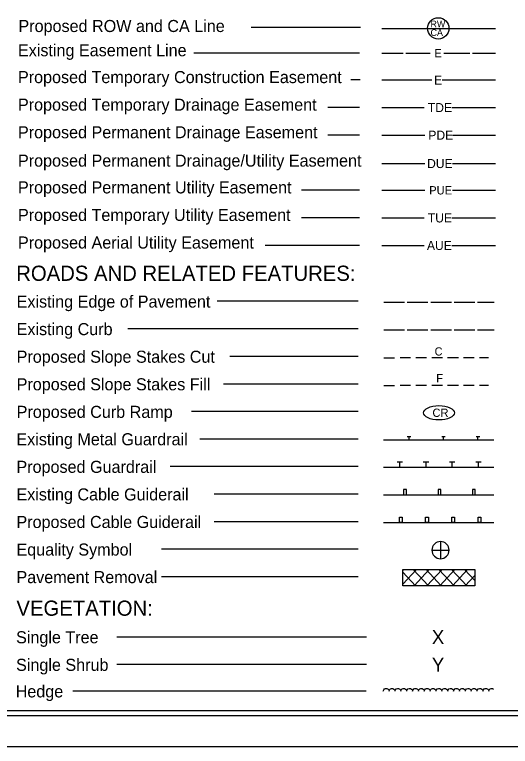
# Model space of a CAD drawing. Extents: x 2041685 to 2043369, y 619046 to 620146.
# Drawn here: x 2042248 to 2042607, y 619046 to 619576 of the extents above; entities that cross this region are included whole.
import ezdxf

# ---------------------------------------------------------------- set-up
doc = ezdxf.new("R2010")
doc.units = 0
for name, color, linetype in [('Prop Easement Permanent Drainage Utility', 7, 'Continuous'), ('Prop WCC CELL', 7, 'Continuous'), ('Sheet Cutting Line CELL', 7, 'Continuous'), ('Sheet Plot Border Inside CELL', 7, 'Continuous'), ('Sheet Plot Border Outside CELL', 7, 'Continuous'), ('Sheet Symbology CELL', 7, 'Continuous')]:
    doc.layers.add(name, color=color, linetype=linetype)

msp = doc.modelspace()

# ---------------------------------------------------------------- linework, layer by layer
at = {"layer": 'Prop Easement Permanent Drainage Utility'}
for p, q in [((2042513.91, 619468.39), (2042545.21, 619468.39)), ((2042565.21, 619468.39), (2042596.41, 619468.39))]:
    msp.add_line(p, q, dxfattribs=at)
at = {"layer": 'Prop WCC CELL'}
msp.add_ellipse((2042555.41, 619287.57), major_axis=(11.21, 0), ratio=0.462467, dxfattribs=at)
at = {"layer": 'Sheet Cutting Line CELL'}
msp.add_line((2041685.03, 619045.62), (2043369.03, 619045.62), dxfattribs=at)
at = {"layer": 'Sheet Plot Border Inside CELL'}
msp.add_lwpolyline([(2041698.03, 619068.07), (2043364.53, 619068.07), (2043364.53, 620123.17), (2041698.03, 620123.17)], close=True, dxfattribs=at)
at = {"layer": 'Sheet Plot Border Outside CELL'}
msp.add_lwpolyline([(2041685.03, 619045.62), (2043369.03, 619045.62), (2043369.03, 620145.62), (2041685.03, 620145.62)], close=True, dxfattribs=at)
at = {"layer": 'Sheet Symbology CELL'}
for p, q in [((2042498.51, 619567.04), (2042419.15, 619567.04)), ((2042513.92, 619566.27), (2042596.42, 619566.27)), ((2042497.88, 619548.42), (2042377.6, 619548.42)), ((2042513.91, 619548.42), (2042529.42, 619548.42)), ((2042531.42, 619548.42), (2042548.92, 619548.42)), ((2042558.92, 619548.42), (2042577.67, 619548.42)), ((2042579.67, 619548.42), (2042596.41, 619548.42)), ((2042498.27, 619528.97), (2042491.59, 619528.97)), ((2042513.91, 619528.97), (2042516.52, 619528.97)), ((2042516.52, 619528.97), (2042550.27, 619528.97)), ((2042557.77, 619528.97), (2042591.52, 619528.97)), ((2042591.52, 619528.97), (2042596.41, 619528.97)), ((2042497.88, 619508.97), (2042474.73, 619508.97)), ((2042513.91, 619508.97), (2042517.26, 619508.97)), ((2042517.26, 619508.97), (2042544.76, 619508.97)), ((2042564.76, 619508.97), (2042592.26, 619508.97)), ((2042592.26, 619508.97), (2042596.41, 619508.97)), ((2042497.88, 619488.97), (2042474.73, 619488.97)), ((2042513.91, 619488.97), (2042517.71, 619488.97)), ((2042517.71, 619488.97), (2042545.21, 619488.97)), ((2042565.21, 619488.97), (2042592.71, 619488.97)), ((2042592.71, 619488.97), (2042596.41, 619488.97)), ((2042497.88, 619448.96), (2042455.74, 619448.96)), ((2042513.91, 619448.96), (2042517.75, 619448.96)), ((2042517.75, 619448.96), (2042545.25, 619448.96)), ((2042565.25, 619448.96), (2042592.75, 619448.96)), ((2042592.75, 619448.96), (2042596.41, 619448.96)), ((2042497.88, 619428.96), (2042455.74, 619428.96)), ((2042513.91, 619428.96), (2042517.26, 619428.96)), ((2042517.26, 619428.96), (2042544.76, 619428.96)), ((2042564.76, 619428.96), (2042592.26, 619428.96)), ((2042592.26, 619428.96), (2042596.41, 619428.96)), ((2042497.88, 619408.96), (2042429.43, 619408.96)), ((2042513.91, 619408.96), (2042517.26, 619408.96)), ((2042517.26, 619408.96), (2042544.76, 619408.96)), ((2042564.76, 619408.96), (2042592.26, 619408.96)), ((2042592.26, 619408.96), (2042596.41, 619408.96)), ((2042496.92, 619368.43), (2042394.57, 619368.43)), ((2042515.45, 619367.86), (2042530.45, 619367.86)), ((2042532.45, 619367.86), (2042547.45, 619367.86)), ((2042549.45, 619367.86), (2042564.45, 619367.86)), ((2042566.45, 619367.86), (2042581.45, 619367.86)), ((2042583.45, 619367.86), (2042595.45, 619367.86)), ((2042496.92, 619348.43), (2042329.77, 619348.43)), ((2042515.45, 619347.86), (2042530.45, 619347.86)), ((2042532.45, 619347.86), (2042547.45, 619347.86)), ((2042549.45, 619347.86), (2042564.45, 619347.86)), ((2042566.45, 619347.86), (2042581.45, 619347.86)), ((2042583.45, 619347.86), (2042595.45, 619347.86)), ((2042496.92, 619328.43), (2042403.73, 619328.43)), ((2042515.45, 619327.38), (2042523.05, 619327.38)), ((2042534.75, 619327.38), (2042527.2, 619327.38)), ((2042546.25, 619327.38), (2042538.65, 619327.38)), ((2042558, 619327.38), (2042550.2, 619327.38)), ((2042569.45, 619327.38), (2042561.7, 619327.38)), ((2042581, 619327.38), (2042573.15, 619327.38)), ((2042591.3, 619327.38), (2042584.9, 619327.38)), ((2042496.92, 619308.43), (2042399.18, 619308.43)), ((2042515.45, 619307.38), (2042523.05, 619307.38)), ((2042534.75, 619307.38), (2042527.2, 619307.38)), ((2042546.25, 619307.38), (2042538.65, 619307.38)), ((2042558, 619307.38), (2042550.2, 619307.38)), ((2042569.45, 619307.38), (2042561.7, 619307.38)), ((2042581, 619307.38), (2042573.15, 619307.38)), ((2042591.3, 619307.38), (2042584.9, 619307.38)), ((2042496.92, 619288.43), (2042375.99, 619288.43)), ((2042496.76, 619268.55), (2042381.93, 619268.55)), ((2042515.29, 619267.98), (2042595.29, 619267.98)), ((2042532.43, 619270.48), (2042534.93, 619270.48)), ((2042533.68, 619267.98), (2042533.68, 619270.48)), ((2042557.43, 619270.48), (2042559.93, 619270.48)), ((2042558.68, 619267.98), (2042558.68, 619270.48)), ((2042582.43, 619270.48), (2042584.93, 619270.48)), ((2042583.68, 619267.98), (2042583.68, 619270.48)), ((2042525.02, 619251.93), (2042529.02, 619251.93)), ((2042527.02, 619247.98), (2042527.02, 619251.93)), ((2042544.02, 619251.93), (2042548.02, 619251.93)), ((2042546.02, 619247.98), (2042546.02, 619251.93)), ((2042563.02, 619251.93), (2042567.02, 619251.93)), ((2042565.02, 619247.98), (2042565.02, 619251.93)), ((2042582.02, 619251.93), (2042586.02, 619251.93)), ((2042584.02, 619247.98), (2042584.02, 619251.93)), ((2042496.76, 619248.55), (2042360.53, 619248.55)), ((2042595.29, 619247.98), (2042515.29, 619247.98)), ((2042496.76, 619228.55), (2042392.46, 619228.55)), ((2042515.29, 619227.98), (2042595.29, 619227.98)), ((2042496.76, 619208.55), (2042392.46, 619208.55)), ((2042515.29, 619207.98), (2042595.29, 619207.98)), ((2042556.52, 619194.21), (2042556.52, 619187.96)), ((2042496.76, 619188.55), (2042354.14, 619188.55)), ((2042550.27, 619187.96), (2042556.52, 619187.96)), ((2042556.52, 619187.96), (2042556.52, 619181.71)), ((2042556.52, 619187.96), (2042562.77, 619187.96)), ((2042529.24, 619173.84), (2042581.34, 619173.84)), ((2042529.24, 619162.14), (2042529.24, 619173.84)), ((2042529.24, 619173.24), (2042529.79, 619173.84)), ((2042529.24, 619163.29), (2042539.09, 619173.84)), ((2042538.49, 619162.14), (2042529.24, 619172.04)), ((2042547.79, 619162.14), (2042536.79, 619173.84)), ((2042537.39, 619162.14), (2042548.39, 619173.84)), ((2042557.04, 619162.14), (2042546.09, 619173.84)), ((2042546.64, 619162.14), (2042557.69, 619173.84)), ((2042566.34, 619162.14), (2042555.34, 619173.84)), ((2042555.94, 619162.14), (2042566.94, 619173.84)), ((2042575.64, 619162.14), (2042564.59, 619173.84)), ((2042565.24, 619162.14), (2042576.19, 619173.84)), ((2042581.34, 619165.89), (2042573.89, 619173.84)), ((2042581.34, 619173.84), (2042581.34, 619162.14)), ((2042496.76, 619168.55), (2042354.14, 619168.55)), ((2042574.49, 619162.14), (2042581.34, 619169.44)), ((2042581.34, 619162.14), (2042529.24, 619162.14)), ((2042502.9, 619124.91), (2042321.78, 619124.91)), ((2042502.9, 619104.91), (2042321.78, 619104.91)), ((2042502.63, 619085.65), (2042289.95, 619085.65)), ((2042515.03, 619085.65), (2042515.33, 619086.6)), ((2042515.33, 619086.6), (2042515.93, 619087.25)), ((2042515.93, 619087.25), (2042516.73, 619087.7)), ((2042516.73, 619087.7), (2042517.68, 619087.7)), ((2042517.68, 619087.7), (2042518.48, 619087.2)), ((2042518.48, 619087.2), (2042519.03, 619086.55)), ((2042519.03, 619086.55), (2042519.23, 619085.7)), ((2042519.28, 619085.65), (2042519.58, 619086.6)), ((2042519.58, 619086.6), (2042520.18, 619087.25)), ((2042520.18, 619087.25), (2042520.98, 619087.7)), ((2042520.98, 619087.7), (2042521.93, 619087.7)), ((2042521.93, 619087.7), (2042522.73, 619087.2)), ((2042522.73, 619087.2), (2042523.28, 619086.55)), ((2042523.28, 619086.55), (2042523.48, 619085.7)), ((2042523.53, 619085.65), (2042523.83, 619086.6)), ((2042523.83, 619086.6), (2042524.43, 619087.25)), ((2042524.43, 619087.25), (2042525.23, 619087.7)), ((2042525.23, 619087.7), (2042526.18, 619087.7)), ((2042526.18, 619087.7), (2042526.98, 619087.2)), ((2042526.98, 619087.2), (2042527.53, 619086.55)), ((2042527.53, 619086.55), (2042527.73, 619085.7)), ((2042527.78, 619085.65), (2042528.08, 619086.6)), ((2042528.08, 619086.6), (2042528.68, 619087.25)), ((2042528.68, 619087.25), (2042529.48, 619087.7)), ((2042529.48, 619087.7), (2042530.43, 619087.7)), ((2042530.43, 619087.7), (2042531.23, 619087.2)), ((2042531.23, 619087.2), (2042531.78, 619086.55)), ((2042531.78, 619086.55), (2042531.98, 619085.7)), ((2042532.03, 619085.65), (2042532.33, 619086.6)), ((2042532.33, 619086.6), (2042532.93, 619087.25)), ((2042532.93, 619087.25), (2042533.73, 619087.7)), ((2042533.73, 619087.7), (2042534.68, 619087.7)), ((2042534.68, 619087.7), (2042535.48, 619087.2)), ((2042535.48, 619087.2), (2042536.03, 619086.55)), ((2042536.03, 619086.55), (2042536.23, 619085.7)), ((2042536.28, 619085.65), (2042536.58, 619086.6)), ((2042536.58, 619086.6), (2042537.18, 619087.25)), ((2042537.18, 619087.25), (2042537.98, 619087.7)), ((2042537.98, 619087.7), (2042538.93, 619087.7)), ((2042538.93, 619087.7), (2042539.73, 619087.2)), ((2042539.73, 619087.2), (2042540.28, 619086.55)), ((2042540.28, 619086.55), (2042540.48, 619085.7)), ((2042540.53, 619085.65), (2042540.83, 619086.6)), ((2042540.83, 619086.6), (2042541.43, 619087.25)), ((2042541.43, 619087.25), (2042542.23, 619087.7)), ((2042542.23, 619087.7), (2042543.18, 619087.7)), ((2042543.18, 619087.7), (2042543.98, 619087.2)), ((2042543.98, 619087.2), (2042544.53, 619086.55)), ((2042544.53, 619086.55), (2042544.73, 619085.7)), ((2042544.78, 619085.65), (2042545.08, 619086.6)), ((2042545.08, 619086.6), (2042545.68, 619087.25)), ((2042545.68, 619087.25), (2042546.48, 619087.7)), ((2042546.48, 619087.7), (2042547.43, 619087.7)), ((2042547.43, 619087.7), (2042548.23, 619087.2)), ((2042548.23, 619087.2), (2042548.78, 619086.55)), ((2042548.78, 619086.55), (2042548.98, 619085.7)), ((2042549.03, 619085.65), (2042549.33, 619086.6)), ((2042549.33, 619086.6), (2042549.93, 619087.25)), ((2042549.93, 619087.25), (2042550.73, 619087.7)), ((2042550.73, 619087.7), (2042551.68, 619087.7)), ((2042551.68, 619087.7), (2042552.48, 619087.2)), ((2042552.48, 619087.2), (2042553.03, 619086.55)), ((2042553.03, 619086.55), (2042553.23, 619085.7)), ((2042553.28, 619085.65), (2042553.58, 619086.6)), ((2042553.58, 619086.6), (2042554.18, 619087.25)), ((2042554.18, 619087.25), (2042554.98, 619087.7)), ((2042554.98, 619087.7), (2042555.93, 619087.7)), ((2042555.93, 619087.7), (2042556.73, 619087.2)), ((2042556.73, 619087.2), (2042557.28, 619086.55)), ((2042557.28, 619086.55), (2042557.48, 619085.7)), ((2042557.53, 619085.65), (2042557.83, 619086.6)), ((2042557.83, 619086.6), (2042558.43, 619087.25)), ((2042558.43, 619087.25), (2042559.23, 619087.7)), ((2042559.23, 619087.7), (2042560.18, 619087.7)), ((2042560.18, 619087.7), (2042560.98, 619087.2)), ((2042560.98, 619087.2), (2042561.53, 619086.55)), ((2042561.53, 619086.55), (2042561.73, 619085.7)), ((2042561.78, 619085.65), (2042562.08, 619086.6)), ((2042562.08, 619086.6), (2042562.68, 619087.25)), ((2042562.68, 619087.25), (2042563.48, 619087.7)), ((2042563.48, 619087.7), (2042564.43, 619087.7)), ((2042564.43, 619087.7), (2042565.23, 619087.2)), ((2042565.23, 619087.2), (2042565.78, 619086.55)), ((2042565.78, 619086.55), (2042565.98, 619085.7)), ((2042566.03, 619085.65), (2042566.33, 619086.6)), ((2042566.33, 619086.6), (2042566.93, 619087.25)), ((2042566.93, 619087.25), (2042567.73, 619087.7)), ((2042567.73, 619087.7), (2042568.68, 619087.7)), ((2042568.68, 619087.7), (2042569.48, 619087.2)), ((2042569.48, 619087.2), (2042570.03, 619086.55)), ((2042570.03, 619086.55), (2042570.23, 619085.7)), ((2042570.28, 619085.65), (2042570.58, 619086.6)), ((2042570.58, 619086.6), (2042571.18, 619087.25)), ((2042571.18, 619087.25), (2042571.98, 619087.7)), ((2042571.98, 619087.7), (2042572.93, 619087.7)), ((2042572.93, 619087.7), (2042573.73, 619087.2)), ((2042573.73, 619087.2), (2042574.28, 619086.55)), ((2042574.28, 619086.55), (2042574.48, 619085.7)), ((2042574.53, 619085.65), (2042574.83, 619086.6)), ((2042574.83, 619086.6), (2042575.43, 619087.25)), ((2042575.43, 619087.25), (2042576.23, 619087.7)), ((2042576.23, 619087.7), (2042577.18, 619087.7)), ((2042577.18, 619087.7), (2042577.98, 619087.2)), ((2042577.98, 619087.2), (2042578.53, 619086.55)), ((2042578.53, 619086.55), (2042578.73, 619085.7)), ((2042578.78, 619085.65), (2042579.08, 619086.6)), ((2042579.08, 619086.6), (2042579.68, 619087.25)), ((2042579.68, 619087.25), (2042580.48, 619087.7)), ((2042580.48, 619087.7), (2042581.43, 619087.7)), ((2042581.43, 619087.7), (2042582.23, 619087.2)), ((2042582.23, 619087.2), (2042582.78, 619086.55)), ((2042582.78, 619086.55), (2042582.98, 619085.7)), ((2042583.03, 619085.65), (2042583.33, 619086.6)), ((2042583.33, 619086.6), (2042583.93, 619087.25)), ((2042583.93, 619087.25), (2042584.73, 619087.7)), ((2042584.73, 619087.7), (2042585.68, 619087.7)), ((2042585.68, 619087.7), (2042586.48, 619087.2)), ((2042586.48, 619087.2), (2042587.03, 619086.55)), ((2042587.03, 619086.55), (2042587.23, 619085.7)), ((2042587.28, 619085.65), (2042587.58, 619086.6)), ((2042587.58, 619086.6), (2042588.18, 619087.25)), ((2042588.18, 619087.25), (2042588.98, 619087.7)), ((2042588.98, 619087.7), (2042589.93, 619087.7)), ((2042589.93, 619087.7), (2042590.73, 619087.2)), ((2042590.73, 619087.2), (2042591.28, 619086.55)), ((2042591.28, 619086.55), (2042591.48, 619085.7)), ((2042591.53, 619085.65), (2042591.83, 619086.6)), ((2042591.83, 619086.6), (2042592.43, 619087.25)), ((2042592.43, 619087.25), (2042593.23, 619087.7)), ((2042593.23, 619087.7), (2042594.18, 619087.7)), ((2042594.18, 619087.7), (2042594.98, 619087.2)), ((2042594.98, 619087.2), (2042595.03, 619087.15))]:
    msp.add_line(p, q, dxfattribs=at)
for points in [[(2043352.03, 620120.62), (2041852.03, 620120.62), (2041852.03, 619071.63), (2043352.03, 619071.63)], [(2042529.77, 619227.98), (2042531.77, 619227.98), (2042531.77, 619231.98), (2042529.77, 619231.98)], [(2042554.77, 619227.98), (2042556.77, 619227.98), (2042556.77, 619231.98), (2042554.77, 619231.98)], [(2042579.77, 619227.98), (2042581.77, 619227.98), (2042581.77, 619231.98), (2042579.77, 619231.98)], [(2042526.76, 619211.98), (2042528.76, 619211.98), (2042528.76, 619207.98), (2042526.76, 619207.98)], [(2042545.76, 619211.98), (2042547.76, 619211.98), (2042547.76, 619207.98), (2042545.76, 619207.98)], [(2042564.76, 619211.98), (2042566.76, 619211.98), (2042566.76, 619207.98), (2042564.76, 619207.98)], [(2042583.76, 619211.98), (2042585.76, 619211.98), (2042585.76, 619207.98), (2042583.76, 619207.98)]]:
    msp.add_lwpolyline(points, close=True, dxfattribs=at)
msp.add_circle((2042554.91, 619566.42), 7.72, dxfattribs=at)
for start, end in [(89.9944, 179.9989), (359.9944, 89.9989), (179.9944, 269.9989), (269.9944, 359.9989)]:
    msp.add_arc((2042556.52, 619187.96), 6.25, start, end, dxfattribs=at)

# ---------------------------------------------------------------- texts
at = {"layer": 'Prop Easement Permanent Drainage Utility'}
msp.add_text('DUE', height=6.55, dxfattribs=at).set_placement((2042546.8, 619465.09))
at = {"layer": 'Prop WCC CELL'}
msp.add_text('CR', height=6, dxfattribs=at).set_placement((2042550.7, 619284.61))
at = {"layer": 'Sheet Symbology CELL'}
for s, height, p in [('Proposed ROW and CA Line', 8.75, (2042250.49, 619563.76)), ('RW', 4.838, (2042549.24, 619567.19)), ('CA', 4.838, (2042549.3, 619560.9)), ('Existing Easement Line', 8.75, (2042250.13, 619546.16)), ('E', 6, (2042552.12, 619545.42)), ('Proposed Temporary Construction Easement', 8.75, (2042250.13, 619526.71)), ('E', 6.55, (2042551.87, 619525.67)), ('Proposed Temporary Drainage Easement', 8.75, (2042250.13, 619506.71)), ('TDE', 6.55, (2042547.36, 619505.67)), ('Proposed Permanent Drainage Easement', 8.75, (2042250.13, 619486.71)), ('PDE', 6.55, (2042547.71, 619485.67)), ('Proposed Permanent Drainage/Utility Easement', 8.75, (2042250.13, 619466.12)), ('Proposed Permanent Utility Easement', 8.75, (2042250.13, 619446.7)), ('PUE', 6, (2042548.35, 619445.96)), ('Proposed Temporary Utility Easement', 8.75, (2042250.13, 619426.7)), ('TUE', 6.55, (2042547.34, 619425.66)), ('Proposed Aerial Utility Easement', 8.75, (2042250.13, 619406.7)), ('AUE', 6.55, (2042546.69, 619405.66)), ('ROADS AND RELATED FEATURES:', 11, (2042248.87, 619383.28)), ('Existing Edge of Pavement', 8.75, (2042249.17, 619363.88)), ('Existing Curb', 8.75, (2042249.17, 619343.88)), ('C', 5.93, (2042552.25, 619329.12)), ('Proposed Slope Stakes Cut', 8.75, (2042249.17, 619323.88)), ('F', 5.93, (2042553.45, 619309.74)), ('Proposed Slope Stakes Fill', 8.75, (2042249.17, 619303.88)), ('Proposed Curb Ramp', 8.75, (2042249.17, 619283.88)), ('Existing Metal Guardrail', 8.75, (2042249.01, 619264)), ('Proposed Guardrail', 8.75, (2042249.03, 619244.01)), ('Existing Cable Guiderail', 8.75, (2042249.03, 619224.01)), ('Proposed Cable Guiderail', 8.75, (2042249.03, 619204.01)), ('Equality Symbol', 8.75, (2042249.03, 619184.01)), ('Pavement Removal', 8.75, (2042249.03, 619164.01)), ('VEGETATION:', 11, (2042249.01, 619140.36)), ('Single Tree', 8.75, (2042248.74, 619120.38)), ('X', 10, (2042550.29, 619119.91)), ('Single Shrub', 8.75, (2042248.74, 619100.38)), ('Y', 10, (2042550.29, 619099.91)), ('Hedge', 8.75, (2042248.47, 619081.12))]:
    msp.add_text(s, height=height, dxfattribs=at).set_placement(p)

doc.saveas('drawing.dxf')
